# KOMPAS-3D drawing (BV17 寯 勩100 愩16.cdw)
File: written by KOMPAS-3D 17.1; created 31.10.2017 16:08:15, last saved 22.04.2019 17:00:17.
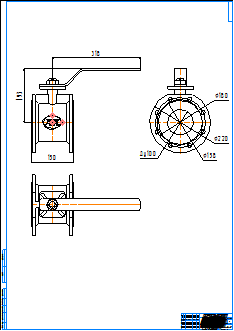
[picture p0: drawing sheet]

Sheet 1: A0, portrait

Title block, sheet 1: name: BV17 МФ Ду100 Ру16; material: Внимание! Данный продукт является объектом авторского права ООО «Торговый Дом АДЛ». / Запрещается изменение, копирование, распространение / (в том числе путем копирования на другие сайты и ресурсы в Интернете) / или любое иное использование информации и объектов без предварительного / согласия правообладателя (ООО «Торговый Дом АДЛ»).; mass: 1; sheets: 1; organisation: ООО "Торговый дом АДЛ"; sheet format: A0; stored path: \\adlc.lan\data\АДЛ_ПКД\3D-модели\ADL production\Краны шаровые серии BV\BV17 МФ Нержавеющие Ру16\KOMPAS 2D\BV17 МФ Ду100 Ру16.cdw

Views: Вид 1, Проекционный вид 2, Проекционный вид 3
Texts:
  kka
  adl
Dimensions and other numbers on the sheet: 150; 318; 193; 100; 220; 180; 158; 1:1; 1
